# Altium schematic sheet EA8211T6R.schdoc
size 127 x 101 mm
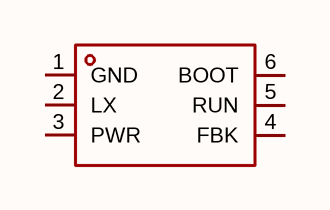
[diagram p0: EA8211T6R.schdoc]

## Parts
U?  ea8211t6r  [SOT-23-6_L2.9-W1.6-P0.95-LS2.8-BR]  (value not drawn)

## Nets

Not connected (* = marked no-connect by the designer): U? 1(GND) 2(LX) 3(PWR) 4(FBK) 5(RUN) 6(BOOT)

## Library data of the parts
U? = ea8211t6r: 功能类型:降压型;工作电压:4.5V~16V;输出电压:800mV~13V;输出电流:3A;输出类型:可调;; Manufacturer: everanalog(申风); AddInBom: yes; ModelId: 18da8f6c14a34920b3e136b5c401a119; ModelName: SOT-23-6_L2.9-W1.6-H1.5-LS2.8-P0.95; ModelTransform: 110.73671,114.173,0,180,0,0,0.001,-0.003,0; Function: 降压型; Output Current: 3A; Frequency - Switching: 500kHz; Synchronous Rectifier: 是; Number of Outputs: 1; Topology: 降压式; Quiescent Current: 600uA; Switch tube (built-in/external): 内置; Output Type: 可调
